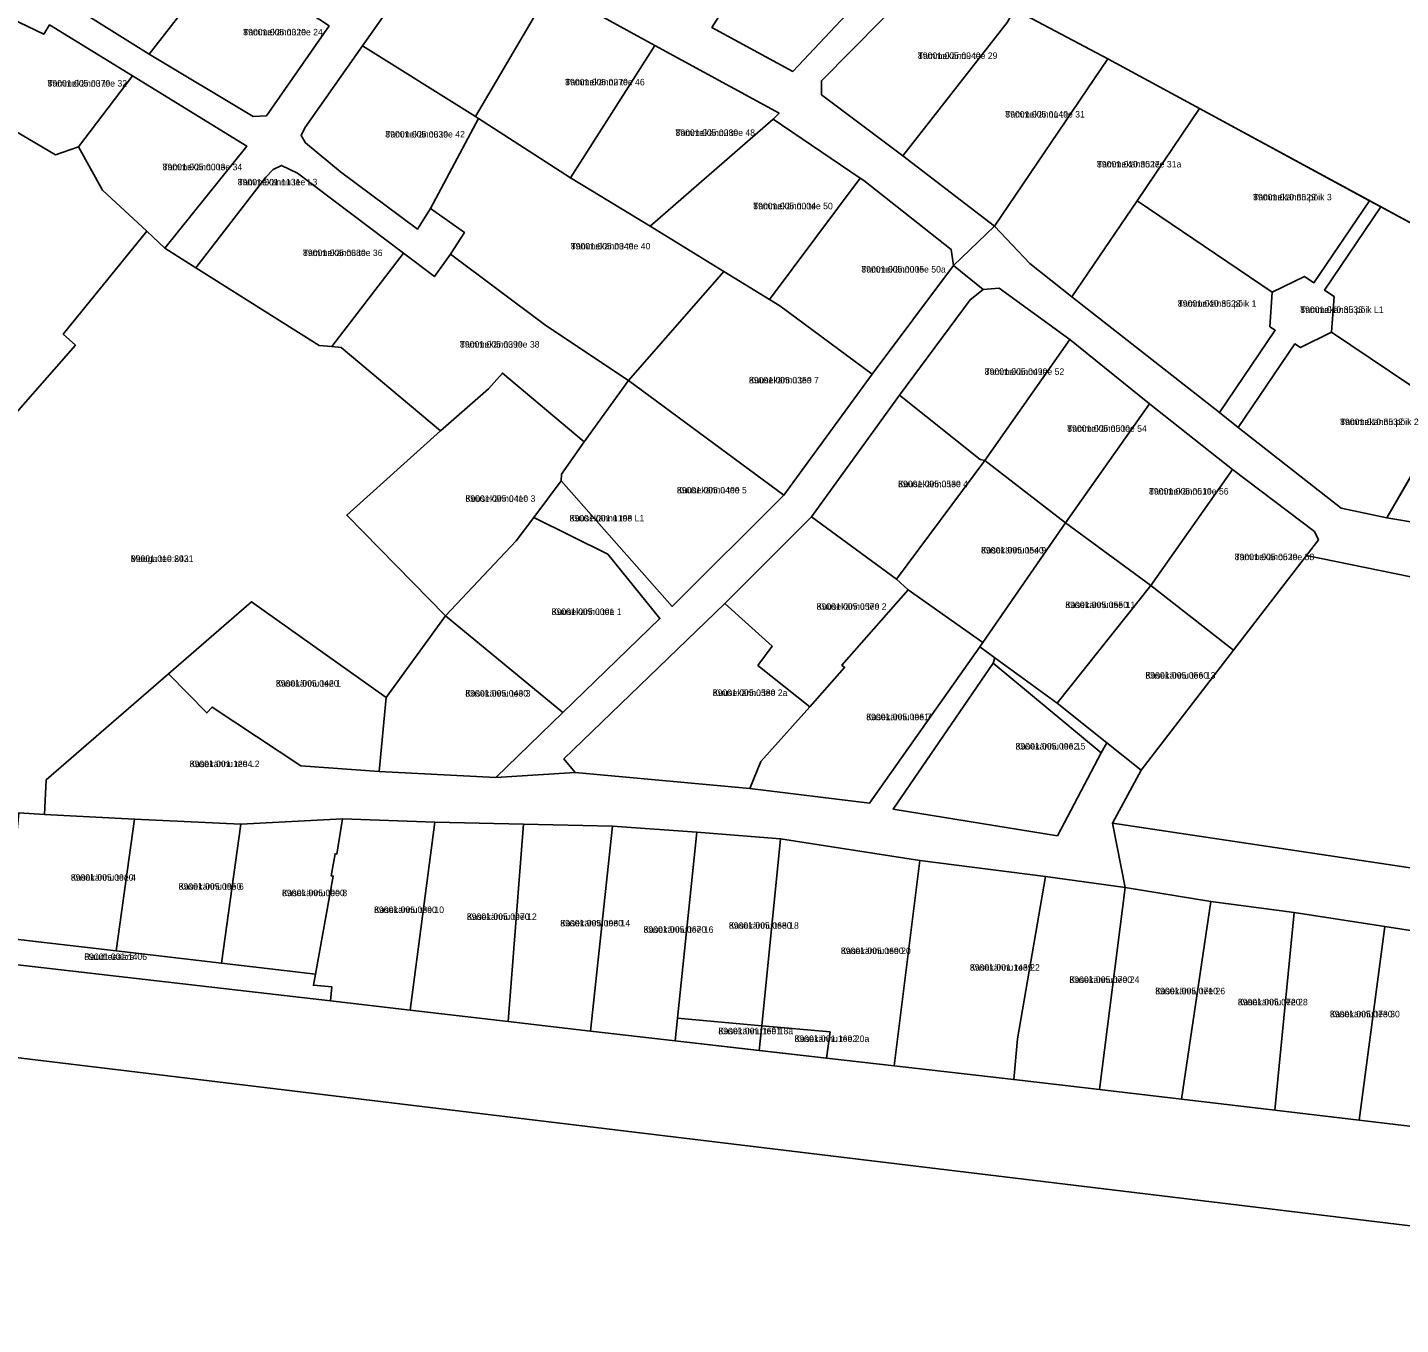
# Model space of a CAD drawing. Extents: x 526849 to 562296, y 6591741 to 6618546.
# Drawn here: x 552840.5 to 553157.9, y 6594481.4 to 6594781.2 of the extents above; entities that cross this region are included whole.
import ezdxf

# ---------------------------------------------------------------- set-up
doc = ezdxf.new("R2010")
doc.units = 0
for name, color, linetype in [('L_AADRESS', 7, 'Continuous'), ('PIIR', 7, 'Continuous'), ('TUNNUS', 7, 'Continuous')]:
    doc.layers.add(name, color=color, linetype=linetype)

msp = doc.modelspace()

# ---------------------------------------------------------------- linework, layer by layer
at = {"layer": 'PIIR'}
for points in [[(553534.3, 6594481.38), (553484.5, 6594491.01), (553464.12, 6594527.28), (553458.46, 6594534.3), (553436.28, 6594561.82), (553392.49, 6594608.35), (553372.68, 6594618.58), (553352.01, 6594629.25), (553348.31, 6594631.16), (553334.14, 6594638.47), (553330.02, 6594640.6), (553305.79, 6594652.47), (553288.5, 6594662), (553267.25, 6594674.38), (553246.36, 6594686.55), (553229.01, 6594696.64), (553210.68, 6594706.7), (553186.25, 6594721.93), (553090.26, 6594773.94), (553068.67, 6594785.39), (553054.03, 6594794.22), (553209.14, 6594936.53), (553211.23, 6594938.44), (553532.6, 6594751.35)], [(552998.76, 6594781.23), (553017.43, 6594771.03), (553044.47, 6594799.81)], [(552932.24, 6594797.21), (552917.96, 6594776.93), (552904.62, 6594757.98), (552903.75, 6594756.23), (552904.76, 6594754.52), (552912.86, 6594747.8), (552930.66, 6594734.6), (552933.69, 6594739.39), (552941.53, 6594733.82), (552938.32, 6594728.77), (552934.59, 6594723.62), (552927.44, 6594729.04), (552902.97, 6594747.53), (552899.26, 6594749.3), (552897.28, 6594748.41), (552895.58, 6594746.6), (552879.42, 6594725.68), (552872.26, 6594730.19), (552891.21, 6594753.77), (552864.83, 6594770), (552845.61, 6594781.81), (552844.29, 6594779.63), (552836.72, 6594783.28)], [(552841.77, 6594791.91), (552868.68, 6594775.04), (552892.69, 6594760.66), (552895.75, 6594760.77), (552910.23, 6594781.55)], [(553044.93, 6594790.04), (553024.04, 6594768.88), (553024.04, 6594765.67), (553042.87, 6594751.55), (553064.04, 6594735.28), (553054.56, 6594726.18), (553054.05, 6594729.9), (553033.84, 6594745.84), (553033.01, 6594746.4), (553012.87, 6594760.04), (553014.28, 6594761.38), (552985.52, 6594777), (552961.47, 6594790.3)], [(552832.32, 6594685.91), (552851.59, 6594707.77), (552848.79, 6594710.34), (552868.08, 6594734.09), (552872.26, 6594730.19), (552879.42, 6594725.68), (552907.96, 6594707.7), (552910.84, 6594707.42), (552913, 6594707.21), (552936.03, 6594687.97), (552914.33, 6594668.48), (552937.13, 6594645.21), (552923.47, 6594626.29), (552892.3, 6594648.44), (552873.08, 6594631.78), (552844.85, 6594607.31), (552844.44, 6594599.28), (552838.49, 6594599.64)], [(553225.09, 6594640.95), (553136.17, 6594659.14), (553138.96, 6594662.76), (553138.04, 6594664.71), (553119.09, 6594678.99), (553099.92, 6594694.17), (553081.45, 6594709.07), (553065.18, 6594720.98), (553061.43, 6594720.62), (553054.56, 6594726.18), (553064.04, 6594735.28), (553072.22, 6594726.67), (553081.97, 6594718.93), (553116.07, 6594692.17), (553120.41, 6594688.76), (553144.19, 6594670.1), (553154.78, 6594667.86), (553190.98, 6594661.74)], [(553174.15, 6594570.3), (553154.29, 6594573.37), (553133.34, 6594576.64), (553114.08, 6594579.2), (553094.25, 6594582.4), (553091.37, 6594597.3), (553197.24, 6594581.4)], [(553229.16, 6594495.91), (552823.08, 6594544.89), (552814.3, 6594546.07), (552801.4, 6594568.75), (552910.6, 6594556.17), (552928.98, 6594554.04), (552951.64, 6594551.4), (552970.64, 6594549.18), (552990.22, 6594546.95), (553025.25, 6594542.95), (553040.9, 6594541.17), (553068.51, 6594538.02), (553088.36, 6594535.7), (553107.29, 6594533.48), (553128.91, 6594530.96), (553148.36, 6594528.65), (553168.4, 6594526.26)]]:
    msp.add_lwpolyline(points, dxfattribs=at)
for points in [[(552854.34, 6594813.94), (552871.14, 6594806.2), (552874.31, 6594804.74), (552886.63, 6594798.11), (552868.68, 6594775.04), (552841.77, 6594791.91)], [(553019.22, 6594813.58), (553044.47, 6594799.81), (553017.43, 6594771.03), (552998.76, 6594781.23)], [(552932.24, 6594797.21), (552938.19, 6594800.93), (552945.77, 6594798.85), (552961.47, 6594790.3), (552944.09, 6594760.62), (552917.96, 6594776.93)], [(552886.63, 6594798.11), (552888.69, 6594796.7), (552900.83, 6594787.79), (552910.23, 6594781.55), (552895.75, 6594760.77), (552892.69, 6594760.66), (552868.68, 6594775.04)], [(553054.03, 6594794.22), (553068.67, 6594785.39), (553067.03, 6594782.37), (553042.87, 6594751.55), (553024.04, 6594765.67), (553024.04, 6594768.88), (553044.93, 6594790.04), (553050.03, 6594796.56)], [(552944.09, 6594760.62), (552961.47, 6594790.3), (552985.52, 6594777), (552966.02, 6594746.41), (552944.81, 6594760.18)], [(553068.67, 6594785.39), (553090.26, 6594773.94), (553064.04, 6594735.28), (553042.87, 6594751.55), (553067.03, 6594782.37)], [(552796.84, 6594781.18), (552825.48, 6594764.43), (552847.01, 6594751.8), (552852.28, 6594753.62), (552857.87, 6594743.63), (552868.08, 6594734.09), (552848.79, 6594710.34), (552851.59, 6594707.77), (552832.32, 6594685.91), (552815.17, 6594672.46), (552817.03, 6594684.75), (552814.5, 6594704.01), (552795.9, 6594714.45), (552788.27, 6594717.68), (552764.34, 6594727.84), (552766.59, 6594733.25), (552787.19, 6594767.49)], [(552836.72, 6594783.28), (552844.29, 6594779.63), (552845.61, 6594781.81), (552864.83, 6594770), (552852.28, 6594753.62), (552847.01, 6594751.8), (552825.48, 6594764.43)], [(552966.02, 6594746.41), (552985.52, 6594777), (553014.28, 6594761.38), (553012.87, 6594760.04), (552984.48, 6594735.27)], [(552904.76, 6594754.52), (552903.75, 6594756.23), (552904.62, 6594757.98), (552917.96, 6594776.93), (552944.09, 6594760.62), (552944.81, 6594760.18), (552933.69, 6594739.39), (552930.66, 6594734.6), (552912.86, 6594747.8)], [(553090.26, 6594773.94), (553111.47, 6594762.45), (553097.02, 6594741.13), (553081.97, 6594718.93), (553072.22, 6594726.67), (553064.04, 6594735.28)], [(552864.83, 6594770), (552891.21, 6594753.77), (552872.26, 6594730.19), (552868.08, 6594734.09), (552857.87, 6594743.63), (552852.28, 6594753.62)], [(553111.47, 6594762.45), (553150.76, 6594741.16), (553137.9, 6594722.18), (553135.74, 6594723.64), (553128.29, 6594720.02), (553097.02, 6594741.13)], [(552938.32, 6594728.77), (552941.53, 6594733.82), (552933.69, 6594739.39), (552944.81, 6594760.18), (552966.02, 6594746.41), (552984.48, 6594735.27), (553001.51, 6594724.8), (552979.43, 6594699.63), (552960.36, 6594712.32)], [(553012.87, 6594760.04), (553033.01, 6594746.4), (553012.02, 6594718.33), (553001.51, 6594724.8), (552984.48, 6594735.27)], [(552895.58, 6594746.6), (552897.28, 6594748.41), (552899.26, 6594749.3), (552902.97, 6594747.53), (552927.44, 6594729.04), (552910.84, 6594707.42), (552907.96, 6594707.7), (552879.42, 6594725.68)], [(553033.01, 6594746.4), (553033.84, 6594745.84), (553054.05, 6594729.9), (553054.56, 6594726.18), (553035.77, 6594701.06), (553014.41, 6594716.86), (553012.02, 6594718.33)], [(553097.02, 6594741.13), (553128.29, 6594720.02), (553127.71, 6594712.04), (553128.96, 6594711.2), (553116.07, 6594692.17), (553081.97, 6594718.93)], [(553150.76, 6594741.16), (553153.41, 6594739.73), (553140.39, 6594720.5), (553142.57, 6594719.01), (553141.98, 6594710.75), (553134.79, 6594707.25), (553133.51, 6594708.11), (553120.41, 6594688.76), (553116.07, 6594692.17), (553128.96, 6594711.2), (553127.71, 6594712.04), (553128.29, 6594720.02), (553135.74, 6594723.64), (553137.9, 6594722.18)], [(553153.41, 6594739.73), (553186.25, 6594721.93), (553173.4, 6594699.98), (553169.06, 6594692.6), (553141.98, 6594710.75), (553142.57, 6594719.01), (553140.39, 6594720.5)], [(552913, 6594707.21), (552910.84, 6594707.42), (552927.44, 6594729.04), (552934.59, 6594723.62), (552938.32, 6594728.77), (552960.36, 6594712.32), (552979.43, 6594699.63), (552969.19, 6594685.39), (552950.32, 6594701.31), (552947.09, 6594697.68), (552936.03, 6594687.97)], [(552948.81, 6594607.86), (552964.29, 6594622.86), (552986.72, 6594644.58), (552974.65, 6594659.46), (552957.55, 6594667.95), (552963.91, 6594676.43), (552989.58, 6594647.37), (553015.37, 6594673.06), (553035.77, 6594701.06), (553054.56, 6594726.18), (553061.43, 6594720.62), (553058.42, 6594718.28), (553042.14, 6594696.23), (553021.73, 6594668.11), (553001.73, 6594648.08), (552964.54, 6594612.11), (552967.1, 6594608.99)], [(553001.51, 6594724.8), (553014.41, 6594716.86), (553035.77, 6594701.06), (553015.37, 6594673.06), (552979.43, 6594699.63)], [(553060.75, 6594681.33), (553042.14, 6594696.23), (553058.42, 6594718.28), (553061.43, 6594720.62), (553065.18, 6594720.98), (553081.45, 6594709.07), (553061.83, 6594681.13)], [(553141.98, 6594710.75), (553169.06, 6594692.6), (553154.78, 6594667.86), (553144.19, 6594670.1), (553120.41, 6594688.76), (553133.51, 6594708.11), (553134.79, 6594707.25)], [(553081.45, 6594709.07), (553099.92, 6594694.17), (553080.48, 6594666.68), (553061.83, 6594681.13)], [(552914.33, 6594668.48), (552936.03, 6594687.97), (552947.09, 6594697.68), (552950.32, 6594701.31), (552969.19, 6594685.39), (552963.98, 6594677.95), (552963.91, 6594676.43), (552957.55, 6594667.95), (552953.47, 6594662.53), (552937.13, 6594645.21)], [(552963.98, 6594677.95), (552969.19, 6594685.39), (552979.43, 6594699.63), (553015.37, 6594673.06), (552989.58, 6594647.37), (552963.91, 6594676.43)], [(553173.45, 6594699.94), (553194.71, 6594682.64), (553190.98, 6594661.74), (553154.78, 6594667.86)], [(553021.73, 6594668.11), (553042.14, 6594696.23), (553060.75, 6594681.33), (553061.83, 6594681.13), (553041.44, 6594653.68)], [(553099.92, 6594694.17), (553119.09, 6594678.99), (553100.21, 6594652.19), (553080.48, 6594666.68)], [(553044.15, 6594651.21), (553041.44, 6594653.68), (553061.83, 6594681.13), (553080.48, 6594666.68), (553061.34, 6594639.02)], [(553119.36, 6594637.23), (553100.21, 6594652.19), (553119.09, 6594678.99), (553138.04, 6594664.71), (553138.96, 6594662.76), (553136.17, 6594659.14)], [(552974.65, 6594659.46), (552986.72, 6594644.58), (552964.29, 6594622.86), (552937.13, 6594645.21), (552953.47, 6594662.53), (552957.55, 6594667.95)], [(553021.73, 6594668.11), (553041.44, 6594653.68), (553044.15, 6594651.21), (553028.8, 6594633.79), (553029.4, 6594633.27), (553021.36, 6594624.19), (553009.37, 6594633.74), (553012.69, 6594638.16), (553001.73, 6594648.08)], [(553064.14, 6594635.53), (553060.65, 6594638.06), (553061.34, 6594639.02), (553080.48, 6594666.68), (553100.21, 6594652.19), (553078.57, 6594625.04)], [(553119.36, 6594637.23), (553136.17, 6594659.14), (553225.09, 6594640.95), (553214.17, 6594633.39), (553197.24, 6594581.4), (553091.37, 6594597.3), (553097.99, 6594609.49)], [(553029.4, 6594633.27), (553028.8, 6594633.79), (553044.15, 6594651.21), (553061.34, 6594639.02), (553060.65, 6594638.06), (553035.18, 6594601.9), (553007.48, 6594605.29), (553010.07, 6594611.5), (553021.36, 6594624.19)], [(553119.36, 6594637.23), (553097.99, 6594609.49), (553090.03, 6594615.86), (553078.57, 6594625.04), (553100.21, 6594652.19)], [(552881.96, 6594622.77), (552873.08, 6594631.78), (552892.3, 6594648.44), (552923.47, 6594626.29), (552921.82, 6594609.24), (552903.68, 6594610.52), (552883.21, 6594624.1)], [(553012.69, 6594638.16), (553009.37, 6594633.74), (553021.36, 6594624.19), (553010.07, 6594611.5), (553007.48, 6594605.29), (552967.1, 6594608.99), (552964.54, 6594612.11), (553001.73, 6594648.08)], [(552923.47, 6594626.29), (552937.13, 6594645.21), (552964.29, 6594622.86), (552948.81, 6594607.86), (552921.82, 6594609.24)], [(552844.85, 6594607.31), (552873.08, 6594631.78), (552881.96, 6594622.77), (552883.21, 6594624.1), (552903.68, 6594610.52), (552921.82, 6594609.24), (552948.81, 6594607.86), (552967.1, 6594608.99), (553007.48, 6594605.29), (553035.18, 6594601.9), (553060.65, 6594638.06), (553064.14, 6594635.53), (553063.79, 6594634.25), (553040.63, 6594600.52), (553078.62, 6594594.36), (553088.72, 6594613.52), (553090.03, 6594615.86), (553097.99, 6594609.49), (553091.37, 6594597.3), (553094.25, 6594582.4), (553075.84, 6594584.96), (553046.81, 6594588.65), (553014.57, 6594593.62), (552995.23, 6594595.22), (552975.73, 6594596.57), (552955.19, 6594597.02), (552934.65, 6594597.47), (552913.37, 6594598.3), (552889.86, 6594597.01), (552865.29, 6594598.23), (552844.44, 6594599.28)], [(553088.72, 6594613.52), (553078.62, 6594594.36), (553040.63, 6594600.52), (553063.79, 6594634.25)], [(552835.77, 6594570.7), (552838.49, 6594599.64), (552844.44, 6594599.28), (552865.29, 6594598.23), (552861.04, 6594567.74)], [(552865.29, 6594598.23), (552889.86, 6594597.01), (552885.34, 6594564.91), (552861.04, 6594567.74)], [(552885.34, 6594564.91), (552889.86, 6594597.01), (552913.37, 6594598.3), (552912.03, 6594590.13), (552911.64, 6594590.2), (552910.72, 6594585.12), (552911.21, 6594585.03), (552907.1, 6594562.37)], [(552913.37, 6594598.3), (552934.65, 6594597.47), (552928.98, 6594554.04), (552910.6, 6594556.17), (552910.87, 6594559.43), (552906.63, 6594559.8), (552907.1, 6594562.37), (552911.21, 6594585.03), (552910.72, 6594585.12), (552911.64, 6594590.2), (552912.03, 6594590.13)], [(552928.98, 6594554.04), (552934.65, 6594597.47), (552955.19, 6594597.02), (552951.64, 6594551.4)], [(552951.64, 6594551.4), (552955.19, 6594597.02), (552975.73, 6594596.57), (552970.64, 6594549.18)], [(552970.64, 6594549.18), (552975.73, 6594596.57), (552995.23, 6594595.22), (552990.76, 6594552.23), (552990.22, 6594546.95)], [(552990.76, 6594552.23), (552995.23, 6594595.22), (553014.57, 6594593.62), (553010.28, 6594550.45)], [(553010.28, 6594550.45), (553014.57, 6594593.62), (553046.81, 6594588.65), (553040.9, 6594541.17), (553025.25, 6594542.95), (553026.07, 6594549.01)], [(553075.84, 6594584.96), (553069.42, 6594547.44), (553068.51, 6594538.02), (553040.9, 6594541.17), (553046.81, 6594588.65)], [(553069.42, 6594547.44), (553075.84, 6594584.96), (553094.25, 6594582.4), (553088.36, 6594535.7), (553068.51, 6594538.02)], [(553088.36, 6594535.7), (553094.25, 6594582.4), (553114.08, 6594579.2), (553107.29, 6594533.48)], [(553107.29, 6594533.48), (553114.08, 6594579.2), (553133.34, 6594576.64), (553128.91, 6594530.96)], [(552910.87, 6594559.43), (552910.6, 6594556.17), (552801.4, 6594568.75), (552797.75, 6594575.13), (552835.77, 6594570.7), (552861.04, 6594567.74), (552885.34, 6594564.91), (552907.1, 6594562.37), (552906.63, 6594559.8)], [(553128.91, 6594530.96), (553133.34, 6594576.64), (553154.29, 6594573.37), (553148.36, 6594528.65)], [(553148.36, 6594528.65), (553154.29, 6594573.37), (553174.15, 6594570.3), (553168.4, 6594526.26)], [(552990.22, 6594546.95), (552990.76, 6594552.23), (553010.28, 6594550.45), (553009.7, 6594544.73)], [(553009.7, 6594544.73), (553010.28, 6594550.45), (553026.07, 6594549.01), (553025.25, 6594542.95)]]:
    msp.add_lwpolyline(points, close=True, dxfattribs=at)

# ---------------------------------------------------------------- texts
at = {"layer": 'L_AADRESS'}
for s, p in [('Tammekännu tee 24', (552890.39, 6594779.38)), ('Tammekännu tee 29', (553046.36, 6594773.93)), ('Tammekännu tee 32', (552845.14, 6594767.54)), ('Tammekännu tee 46', (552964.81, 6594767.83)), ('Tammekännu tee 31', (553066.56, 6594760.39)), ('Tammekännu tee 42', (552923.24, 6594755.77)), ('Tammekännu tee 48', (552990.31, 6594756.13)), ('Tammekännu tee 34', (552871.75, 6594748.21)), ('Tammekännu tee 31a', (553087.75, 6594748.85)), ('Tammekännu tee L3', (552889.12, 6594744.71)), ('Tammekännu põik 3', (553123.86, 6594741.24)), ('Tammekännu tee 50', (553008.29, 6594739.18)), ('Tammekännu tee 36', (552904.2, 6594728.36)), ('Tammekännu tee 40', (552966.12, 6594729.9)), ('Tammekännu tee 50a', (553033.29, 6594724.55)), ('Tammekännu põik 1', (553106.46, 6594716.65)), ('Tammekännu põik L1', (553134.74, 6594715.22)), ('Tammekännu tee 38', (552940.49, 6594707.21)), ('Tammekännu tee 52', (553061.8, 6594700.9)), ('Kuusekännu tee 7', (553007.3, 6594698.93)), ('Tammekännu tee 54', (553080.88, 6594687.74)), ('Tammekännu põik 2', (553143.97, 6594689.3)), ('Kuusekännu tee 4', (553041.78, 6594674.94)), ('Kuusekännu tee 3', (552941.76, 6594671.56)), ('Kuusekännu tee 5', (552990.64, 6594673.5)), ('Tammekännu tee 56', (553099.79, 6594673.24)), ('Kuusekännu tee L1', (552965.82, 6594667.02)), ('Kasekännu tee 9', (553060.96, 6594659.62)), ('Tammekännu tee 58', (553119.59, 6594658.07)), ('Muuga tee 202', (552864.39, 6594657.67)), ('Kuusekännu tee 1', (552961.68, 6594645.4)), ('Kuusekännu tee 2', (553022.94, 6594646.6)), ('Kasekännu tee 11', (553080.43, 6594646.99)), ('Kasekännu tee 13', (553098.96, 6594630.69)), ('Kasekännu tee 1', (552897.93, 6594628.84)), ('Kasekännu tee 3', (552941.74, 6594626.54)), ('Kuusekännu tee 2a', (552998.92, 6594626.68)), ('Kasekännu tee 7', (553034.41, 6594621.08)), ('Kasekännu tee 15', (553068.94, 6594614.3)), ('Kasekännu tee L2', (552878, 6594610.23)), ('Kasekännu tee 4', (552850.53, 6594583.97)), ('Kasekännu tee 6', (552875.45, 6594581.89)), ('Kasekännu tee 8', (552899.36, 6594580.4)), ('Kasekännu tee 10', (552920.64, 6594576.51)), ('Kasekännu tee 12', (552942.08, 6594574.91)), ('Kasekännu tee 14', (552963.68, 6594573.41)), ('Kasekännu tee 18', (553002.66, 6594572.87)), ('Kasekännu tee 16', (552982.93, 6594571.93)), ('Kasekännu tee 20', (553028.55, 6594567.02)), ('Raudteeääre', (552853.65, 6594565.65)), ('Kasekännu tee 22', (553058.37, 6594563.18)), ('Kasekännu tee 24', (553081.38, 6594560.35)), ('Kasekännu tee 26', (553101.22, 6594557.73)), ('Kasekännu tee 28', (553120.32, 6594555.17)), ('Kasekännu tee 30', (553141.6, 6594552.4)), ('Kasekännu tee 18a', (553000.23, 6594548.48)), ('Kasekännu tee 20a', (553017.83, 6594546.7))]:
    msp.add_text(s, height=1.5, dxfattribs=at).set_placement(p)
at = {"layer": 'TUNNUS'}
for s, p in [('89001:005:0320', (552890.39, 6594779.38)), ('89001:005:0940', (553046.36, 6594773.93)), ('89001:005:0370', (552845.14, 6594767.54)), ('89001:005:0270', (552964.81, 6594767.83)), ('89001:005:0140', (553066.56, 6594760.39)), ('89001:005:0330', (552923.24, 6594755.77)), ('89001:005:0280', (552990.31, 6594756.13)), ('89001:005:0003', (552871.75, 6594748.21)), ('89001:010:3527', (553087.75, 6594748.85)), ('89001:001:1131', (552889.12, 6594744.71)), ('89001:010:3529', (553123.86, 6594741.24)), ('89001:005:0004', (553008.29, 6594739.18)), ('89001:005:0380', (552904.2, 6594728.36)), ('89001:005:0340', (552966.12, 6594729.9)), ('89001:005:0005', (553033.29, 6594724.55)), ('89001:010:3528', (553106.46, 6594716.65)), ('89001:010:3533', (553134.74, 6594715.22)), ('89001:005:0390', (552940.49, 6594707.21)), ('89001:005:0490', (553061.8, 6594700.9)), ('89001:005:0350', (553007.3, 6594698.93)), ('89001:005:0500', (553080.88, 6594687.74)), ('89001:010:3532', (553143.97, 6594689.3)), ('89001:005:0530', (553041.78, 6594674.94)), ('89001:005:0410', (552941.76, 6594671.56)), ('89001:005:0400', (552990.64, 6594673.5)), ('89001:005:0510', (553099.79, 6594673.24)), ('89001:001:1198', (552965.82, 6594667.02)), ('89001:005:0540', (553060.96, 6594659.62)), ('89001:005:0520', (553119.59, 6594658.07)), ('89001:010:8431', (552864.39, 6594657.67)), ('89001:005:0001', (552961.68, 6594645.4)), ('89001:005:0570', (553022.94, 6594646.6)), ('89001:005:0550', (553080.43, 6594646.99)), ('89001:005:0560', (553098.96, 6594630.69)), ('89001:005:0420', (552897.93, 6594628.84)), ('89001:005:0430', (552941.74, 6594626.54)), ('89001:005:0580', (552998.92, 6594626.68)), ('89001:005:0961', (553034.41, 6594621.08)), ('89001:005:0962', (553068.94, 6594614.3)), ('89001:001:1204', (552878, 6594610.23)), ('89001:005:0910', (552850.53, 6594583.97)), ('89001:005:0950', (552875.45, 6594581.89)), ('89001:005:0900', (552899.36, 6594580.4)), ('89001:005:0890', (552920.64, 6594576.51)), ('89001:005:0970', (552942.08, 6594574.91)), ('89001:005:0980', (552963.68, 6594573.41)), ('89001:005:0680', (553002.66, 6594572.87)), ('89001:005:0670', (552982.93, 6594571.93)), ('89001:005:0690', (553028.55, 6594567.02)), ('89001:001:1406', (552853.65, 6594565.65)), ('89001:001:1439', (553058.37, 6594563.18)), ('89001:005:0700', (553081.38, 6594560.35)), ('89001:005:0710', (553101.22, 6594557.73)), ('89001:005:0720', (553120.32, 6594555.17)), ('89001:005:0730', (553141.6, 6594552.4)), ('89001:001:1691', (553000.23, 6594548.48)), ('89001:001:1692', (553017.83, 6594546.7))]:
    msp.add_text(s, height=1.5, dxfattribs=at).set_placement(p)

doc.saveas('drawing.dxf')
